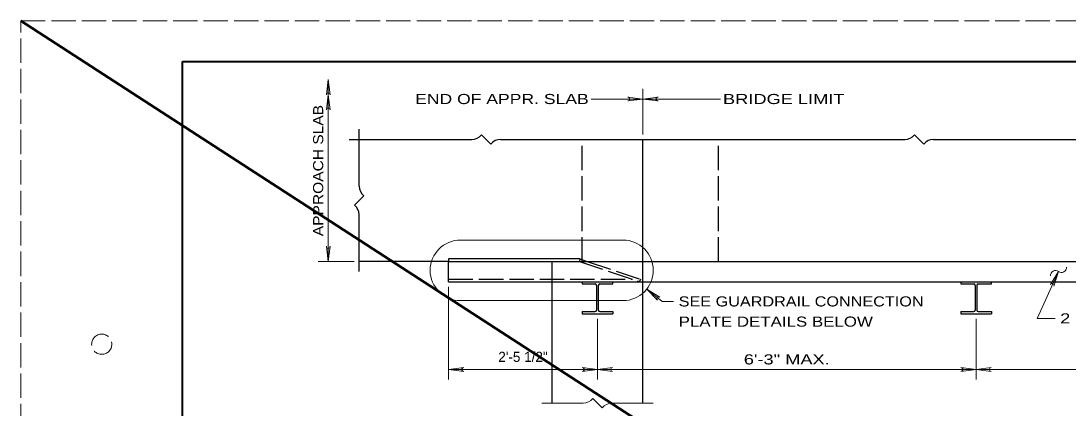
# Model space of a CAD drawing. Extents: x 1285 to 1427, y 1365 to 1427.
# Drawn here: x 1285.33 to 1302.62, y 1420.28 to 1426.67 of the extents above; entities that cross this region are included whole.
import ezdxf
from ezdxf.enums import TextEntityAlignment as Align

# ---------------------------------------------------------------- set-up
doc = ezdxf.new("R2010")
doc.units = 0
doc.header["$LTSCALE"] = 0.067
doc.linetypes.add('LONG_DASHED', pattern=[7.5, 6, -1.5])
for name, color, linetype, lineweight in [('1', 7, 'Continuous', 40), ('42', 7, 'Continuous', 25), ('43', 7, 'Continuous', 25), ('44', 7, 'Continuous', 13), ('47', 7, 'Continuous', 13), ('50', 7, 'LONG_DASHED', 13)]:
    doc.layers.add(name, color=color, linetype=linetype, lineweight=lineweight)
doc.layers.add('41', color=7, linetype='Continuous')

msp = doc.modelspace()

# ---------------------------------------------------------------- linework, layer by layer
at = {"layer": '1', "lineweight": 53}
msp.add_line((1285.33333, 1426.66667), (1330.66667, 1397.33333), dxfattribs=at)
at = {"layer": '1', "linetype": 'LONG_DASHED', "lineweight": 13}
msp.add_lwpolyline([(1285.33333, 1426.66667), (1330.66667, 1426.66667), (1330.66667, 1397.33333), (1285.33333, 1397.33333)], close=True, dxfattribs=at)
at = {"layer": '1'}
msp.add_lwpolyline([(1288, 1426), (1330, 1426), (1330, 1398), (1288, 1398)], close=True, dxfattribs=at)
at = {"layer": '42'}
for p, q in [((1290.91656, 1423.94189), (1290.91656, 1424.87889)), ((1292.93544, 1424.78967), (1293.09011, 1424.63478)), ((1300.08167, 1424.78967), (1300.23633, 1424.63478)), ((1290.74989, 1424.71222), (1292.778, 1424.71222)), ((1293.24844, 1424.71222), (1299.92233, 1424.71222)), ((1295.59989, 1422.69833), (1295.59989, 1424.71222)), ((1300.39467, 1424.71222), (1305.05289, 1424.71222)), ((1290.994, 1423.78256), (1290.83911, 1423.62789)), ((1290.91656, 1422.53167), (1290.91656, 1423.46956)), ((1292.39156, 1422.69833), (1290.91656, 1422.69833)), ((1292.39156, 1422.69833), (1308.50211, 1422.69833)), ((1292.39156, 1422.365), (1292.39156, 1422.69833)), ((1293.55756, 1422.69833), (1294.55067, 1422.69833)), ((1294.55756, 1422.74), (1294.55067, 1422.69833)), ((1294.55756, 1422.74), (1294.68256, 1422.69833)), ((1292.39156, 1422.365), (1308.50211, 1422.365)), ((1294.09989, 1420.36067), (1294.09989, 1422.365)), ((1294.59656, 1422.365), (1295.10322, 1422.365)), ((1294.59656, 1422.365), (1294.59656, 1422.32711)), ((1295.10322, 1422.32711), (1295.10322, 1422.365)), ((1295.59989, 1420.36067), (1295.59989, 1422.365)), ((1300.84656, 1422.365), (1301.35322, 1422.365)), ((1300.84656, 1422.365), (1300.84656, 1422.32711)), ((1301.35322, 1422.32711), (1301.35322, 1422.365)), ((1294.59656, 1422.32711), (1294.81322, 1422.32711)), ((1294.83656, 1422.30378), (1294.83656, 1421.89456)), ((1294.86322, 1422.30378), (1294.86322, 1421.89456)), ((1294.88656, 1422.32711), (1295.10322, 1422.32711)), ((1300.84656, 1422.32711), (1301.06322, 1422.32711)), ((1301.08656, 1422.30378), (1301.08656, 1421.89456)), ((1301.11322, 1422.30378), (1301.11322, 1421.89456)), ((1301.13656, 1422.32711), (1301.35322, 1422.32711)), ((1294.59656, 1421.87122), (1294.59656, 1421.83333)), ((1294.59656, 1421.87122), (1294.81322, 1421.87122)), ((1294.59656, 1421.83333), (1295.10322, 1421.83333)), ((1294.88656, 1421.87122), (1295.10322, 1421.87122)), ((1295.10322, 1421.87122), (1295.10322, 1421.83333)), ((1300.84656, 1421.87122), (1300.84656, 1421.83333)), ((1300.84656, 1421.87122), (1301.06322, 1421.87122)), ((1300.84656, 1421.83333), (1301.35322, 1421.83333)), ((1301.13656, 1421.87122), (1301.35322, 1421.87122)), ((1301.35322, 1421.87122), (1301.35322, 1421.83333))]:
    msp.add_line(p, q, dxfattribs=at)
msp.add_lwpolyline([(1294.55756, 1422.74), (1292.39156, 1422.74), (1292.39156, 1422.69833)], dxfattribs=at)
for centre, radius, start, end in [((1292.77707, 1424.91285), 0.20062, 270, 322.10148), ((1299.9233, 1424.91285), 0.20062, 270, 322.10148), ((1293.24848, 1424.51159), 0.20062, 90, 142.10148), ((1300.3947, 1424.51159), 0.20062, 90, 142.10148), ((1291.11718, 1423.94093), 0.20062, 180, 232.10148), ((1290.71593, 1423.46952), 0.20062, 360, 52.10148), ((1294.81322, 1422.30378), 0.02333, 0, 90), ((1294.88656, 1422.30378), 0.02333, 90, 180), ((1301.06322, 1422.30378), 0.02333, 0, 90), ((1301.13656, 1422.30378), 0.02333, 90, 180), ((1294.81322, 1421.89456), 0.02333, 270, 0), ((1294.88656, 1421.89456), 0.02333, 180, 270), ((1301.06322, 1421.89456), 0.02333, 270, 0), ((1301.13656, 1421.89456), 0.02333, 180, 270)]:
    msp.add_arc(centre, radius, start, end, dxfattribs=at)
at = {"layer": '43', "linetype": 'LONG_DASHED'}
for p, q in [((1294.59989, 1422.69833), (1294.59989, 1424.71222)), ((1296.84989, 1422.69833), (1296.84989, 1424.71222)), ((1294.09989, 1422.365), (1294.09989, 1422.69833)), ((1294.55067, 1422.69833), (1295.54433, 1422.36711)), ((1294.68256, 1422.69833), (1295.55756, 1422.40667)), ((1295.59989, 1422.365), (1295.59989, 1422.69833)), ((1292.39156, 1422.40667), (1295.42567, 1422.40667)), ((1295.55756, 1422.40667), (1295.54433, 1422.36711))]:
    msp.add_line(p, q, dxfattribs=at)
at = {"layer": '44'}
for p, q in [((1295.59989, 1425.37889), (1294.74789, 1425.37889)), ((1295.59989, 1425.37889), (1295.34989, 1425.41011)), ((1295.84989, 1425.41011), (1295.59989, 1425.37889)), ((1295.59989, 1425.37889), (1295.84989, 1425.34767)), ((1294.77256, 1420.43811), (1294.92722, 1420.28322))]:
    msp.add_line(p, q, dxfattribs=at)
msp.add_lwpolyline([(1295.34989, 1425.34767), (1295.59989, 1425.37889), (1296.88033, 1425.37889)], dxfattribs=at)
for centre, radius, start, end in [((1295.34989, 1425.37889), 0.03122, 270, 90), ((1295.84989, 1425.37889), 0.03122, 90, 270), ((1294.61419, 1420.56129), 0.20062, 270, 322.10148), ((1295.08559, 1420.16004), 0.20062, 90, 142.10148)]:
    msp.add_arc(centre, radius, start, end, dxfattribs=at)
at = {"layer": '47'}
for p, q in [((1290.40578, 1422.69833), (1290.40578, 1425.69833)), ((1295.59989, 1424.79556), (1295.59989, 1425.54556)), ((1292.58833, 1423.05244), (1295.271, 1423.05244)), ((1290.83322, 1422.69833), (1290.23911, 1422.69833)), ((1292.39156, 1422.28167), (1292.39156, 1420.75)), ((1292.58833, 1422.05244), (1295.271, 1422.05244)), ((1294.84989, 1421.75), (1294.84989, 1420.75)), ((1301.09989, 1421.75), (1301.09989, 1420.75)), ((1292.39156, 1420.91667), (1294.84989, 1420.91667)), ((1294.84989, 1420.91667), (1301.09989, 1420.91667)), ((1301.09989, 1420.91667), (1307.34989, 1420.91667)), ((1293.93322, 1420.36067), (1294.61322, 1420.36067)), ((1295.08556, 1420.36067), (1295.76656, 1420.36067))]:
    msp.add_line(p, q, dxfattribs=at)
for points in [[(1290.37456, 1425.44833), (1290.40578, 1425.69833), (1290.437, 1425.44833)], [(1290.37456, 1425.19833), (1290.40578, 1425.44833), (1290.437, 1425.19833)], [(1295.84989, 1425.34767), (1295.59989, 1425.37889), (1295.84989, 1425.41011)], [(1290.437, 1422.94833), (1290.40578, 1422.69833), (1290.37456, 1422.94833)], [(1302.40411, 1421.75967), (1302.10967, 1421.75967), (1302.45989, 1422.53333)], [(1302.32833, 1422.31844), (1302.45989, 1422.53333), (1302.38522, 1422.29267)], [(1296.10733, 1422.03956), (1295.91578, 1422.03956), (1295.66233, 1422.24111)], [(1295.83856, 1422.06111), (1295.66233, 1422.24111), (1295.87744, 1422.10989)], [(1292.64156, 1420.88544), (1292.39156, 1420.91667), (1292.64156, 1420.94789)], [(1294.59989, 1420.94789), (1294.84989, 1420.91667), (1294.59989, 1420.88544)], [(1295.09989, 1420.88544), (1294.84989, 1420.91667), (1295.09989, 1420.94789)], [(1300.84989, 1420.94789), (1301.09989, 1420.91667), (1300.84989, 1420.88544)], [(1301.34989, 1420.88544), (1301.09989, 1420.91667), (1301.34989, 1420.94789)]]:
    msp.add_lwpolyline(points, dxfattribs=at)
for centre, radius, start, end in [((1290.40584, 1425.44836), 0.03122, 0, 180), ((1295.84986, 1425.37895), 0.03122, 90, 270), ((1290.40584, 1425.19836), 0.03122, 0, 180), ((1292.58833, 1422.55244), 0.5, 90, 270), ((1295.27104, 1422.55244), 0.5, 270, 90), ((1290.40572, 1422.9483), 0.03122, 180, 0), ((1302.41073, 1422.46604), 0.08333, 53.85214, 183.85214), ((1302.50904, 1422.60062), 0.08333, 233.85214, 3.85214), ((1302.35686, 1422.30559), 0.03122, 335.64476, 155.64476), ((1295.85801, 1422.08557), 0.03122, 51.50599, 231.50599), ((1292.64152, 1420.91672), 0.03122, 90, 270), ((1294.59992, 1420.91661), 0.03122, 270, 90), ((1295.09986, 1420.91672), 0.03122, 90, 270), ((1300.84992, 1420.91661), 0.03122, 270, 90), ((1301.34986, 1420.91672), 0.03122, 90, 270)]:
    msp.add_arc(centre, radius, start, end, dxfattribs=at)
at = {"layer": '50'}
msp.add_circle((1286.66667, 1421.33333), 0.16667, dxfattribs=at)

# ---------------------------------------------------------------- texts
at = {"layer": '41', "width": 1.15}
msp.add_text('APPROACH SLAB', height=0.1667, rotation=90, dxfattribs=at).set_placement((1290.32244, 1424.19839), align=Align.CENTER)
at = {"layer": '41'}
for s, width, p in [('SEE GUARDRAIL CONNECTION ', 1.2, (1296.19067, 1421.95622)), ('2 - TS 8 x 4 x 5/16 TUBING', 1.35, (1302.48744, 1421.67633)), ('PLATE DETAILS BELOW', 1.25, (1296.19067, 1421.62289))]:
    msp.add_text(s, height=0.1667, dxfattribs=dict(at, width=width)).set_placement(p)
msp.add_text('2\'-5 1/2"', height=0.1667, dxfattribs=at).set_placement((1293.62061, 1421.04167), align=Align.CENTER)
at = {"layer": '44', "width": 1.3}
msp.add_text('END OF APPR. SLAB', height=0.1667, dxfattribs=at).set_placement((1294.70622, 1425.29556), align=Align.RIGHT)
at = {"layer": '44', "width": 1.35}
msp.add_text('BRIDGE LIMIT', height=0.1667, dxfattribs=at).set_placement((1296.922, 1425.29556))
msp.add_text('6\'-3" MAX.', height=0.1667, dxfattribs=at).set_placement((1297.97489, 1421), align=Align.CENTER)

doc.saveas('drawing.dxf')
